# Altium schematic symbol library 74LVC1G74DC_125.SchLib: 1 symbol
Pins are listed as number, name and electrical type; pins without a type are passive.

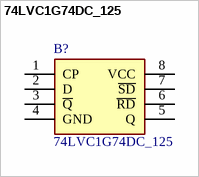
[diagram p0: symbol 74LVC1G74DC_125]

## 74LVC1G74DC_125
designator B?
74LVC1G74 - Single D-type flip-flop with set and reset; positive edge trigger@en-us; Manufacturer_Name: Nexperia; Manufacturer_Part_Number: 74LVC1G74DC,125; Geometry.Height: 1mm
footprint SOP50P310X100-8N
pins: 1 CP, 2 D, 3 ~{Q}, 4 GND, 5 Q, 6 ~{RD}, 7 ~{SD}, 8 VCC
